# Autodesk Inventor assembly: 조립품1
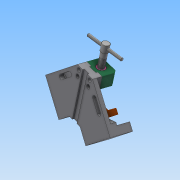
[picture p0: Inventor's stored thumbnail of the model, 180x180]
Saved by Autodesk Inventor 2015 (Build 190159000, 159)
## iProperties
Created: 2019-04
Part Number: 조립품1
Document SubType Name: Assembly
Designer: SCD-A01
Author: SCD-A01
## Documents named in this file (11)
- C:\Users\SCD-A01\Desktop\권원태\조립품1.iam
- C:\Users\SCD-A01\Desktop\권원태\본체.ipt
- C:\Users\SCD-A01\Desktop\권원태\490408V1003\서포트.ipt
- C:\Users\SCD-A01\Desktop\권원태\490408V1003\부시.ipt
- C:\Users\SCD-A01\Desktop\권원태\490408V1003\볼트 M4x16.ipt
- C:\Users\SCD-A01\Desktop\권원태\490408V1003\리드스크류.ipt
- C:\Users\SCD-A01\Desktop\권원태\490408V1003\멈춤나사 M4x10.ipt
- C:\Users\SCD-A01\Desktop\권원태\490408V1003\핸들.ipt
- C:\Users\SCD-A01\Desktop\권원태\490408V1003\멈춤나사 M4x5.ipt
- C:\Users\SCD-A01\Desktop\권원태\490408V1003\조.ipt
- C:\Users\SCD-A01\Desktop\권원태\490408V1003\평행 핀 2.5x24.ipt
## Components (1 placed, 1 different names)
1. 핸들:1
